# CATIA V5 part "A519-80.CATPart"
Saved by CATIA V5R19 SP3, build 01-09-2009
Part number: A519-80
Bounding box of the stored display mesh (mm): x -39.876 to 39.876, y -40 to 40, z 0 to 90
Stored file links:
  C:\Users\d.catalano\Desktop\CATALOGO CAD\04 MOLLE\A519\A519-80.CATPart
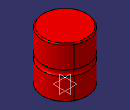
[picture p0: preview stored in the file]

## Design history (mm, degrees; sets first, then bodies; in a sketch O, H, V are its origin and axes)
Body1 "A519-80" (main body)
  Sketch1 on yz-plane, origin (0, 0, 0), H (0, 1, 0), V (0, 0, 1)
    line L1 (0, 0) -> (38, 0)
    line L2 (40, 2) -> (40, 39.9049)
    line L3 (38, 90) -> (0, 90)
    line L4 (0, 90) -> (0, 0)
    construction line L5 (-5.6038, 45) -> (28.5463, 45)
    arc A1 centre (44.8, 45) radius 7 from (40, 50.0951) to (40, 39.9049) ccw
    point P2 (44.8, 45)
    construction line L6 (37.8, 49.6338) -> (37.8, -12.4196)
    line L7 (40, 50.0951) -> (40, 88)
    arc A2 centre (38, 88) radius 2 from (38, 90) to (40, 88) cw
    arc A3 centre (38, 2) radius 2 from (38, 0) to (40, 2) ccw
    distance L4 L2 = 40
    distance L1 L3 = 90
    distance L5 L3 = 45
    radius A1 = 7
    distance L2 L6 = 2.2
    radius A2 = 2
    radius A3 = 2
    horizontal: L1 H, L3 H, L5 H
    vertical: L2 V, L4 V, L6 V, L7 V
    coincidence: P2 L5, L2 L7
    tangency: A1 L6, A2 L3, A2 L7, A3 L1, A3 L2
  Shaft1 "Albero": profile Sketch1, axis Sketch1.L4, angle 360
